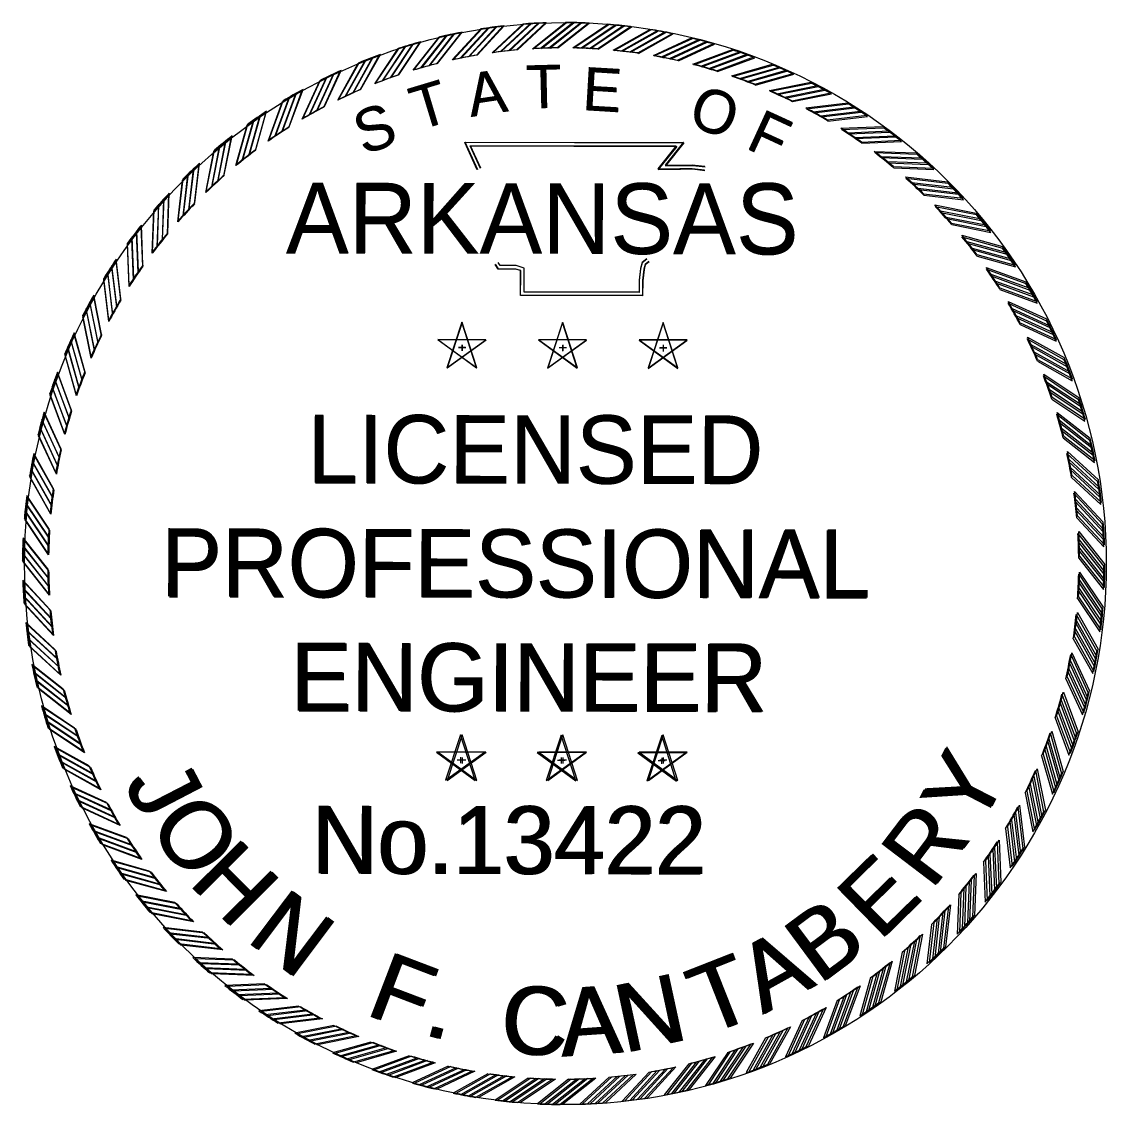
# Model space of a CAD drawing. Extents: x 0 to 19, y -0.6 to 11.5.
# Drawn here: x 17.82 to 19.023, y 7.715 to 8.916 of the extents above; entities that cross this region are included whole.
import ezdxf

# ---------------------------------------------------------------- set-up
doc = ezdxf.new("R2010")
doc.units = 0
for name, color, linetype in [('Default', 7, 'Continuous'), ('G-ANNO-STMP', 7, 'Continuous'), ('G-No Plot-Stamp-1', 7, 'Continuous')]:
    doc.layers.add(name, color=color, linetype=linetype)

# ---------------------------------------------------------------- blocks, each defined once
blk = doc.blocks.new('STAR')
at = {"layer": 'Default'}
for p, q in [((-0.0001, 0.0615), (-0.0366, -0.0504)), ((0.0362, -0.0503), (0, 0.0617)), ((0.0587, 0.0188), (-0.059, 0.0189)), ((-0.0589, 0.0188), (0.0363, -0.0505)), ((-0.0365, -0.0503), (0.0589, 0.0188)), ((-0.0085, 0), (0.009, 0)), ((0, 0.0063), (0, -0.0085))]:
    blk.add_line(p, q, dxfattribs=at)
blk = doc.blocks.new('RP')
at = {"layer": 'Default'}
for p, q in [((-0.0781, 1.2656), (0.003, 1.33)), ((-0.058, 1.2667), (0.0216, 1.3299)), ((-0.0375, 1.2674), (0.0405, 1.3294)), ((-0.0176, 1.2679), (0.059, 1.3287))]:
    blk.add_line(p, q, dxfattribs=at)
for radius, start, end in [(1.33, 87.4562, 89.8699), (1.268, 90.7933, 93.5307)]:
    blk.add_arc((0, 0), radius, start, end, dxfattribs=at)

msp = doc.modelspace()

# ---------------------------------------------------------------- linework, layer by layer
at = {"layer": 'G-ANNO-STMP'}
for points in [[(18.3256, 8.7521), (18.3116, 8.7824), (18.5542, 8.7826), (18.5339, 8.7571), (18.5504, 8.7573), (18.5641, 8.7575), (18.5779, 8.756)], [(18.3261, 8.7522), (18.3121, 8.7827), (18.5547, 8.782), (18.5344, 8.7566), (18.5509, 8.7567), (18.5646, 8.7569), (18.5784, 8.7553)], [(18.3291, 8.7537), (18.3176, 8.7786), (18.5462, 8.7787), (18.5258, 8.7532), (18.5504, 8.7535), (18.564, 8.7537), (18.5775, 8.7522)], [(18.3295, 8.7538), (18.3181, 8.7788), (18.5468, 8.7781), (18.5263, 8.7526), (18.5509, 8.7529), (18.5644, 8.753), (18.5779, 8.7515)], [(18.5135, 8.6534), (18.5084, 8.6492), (18.5066, 8.6427), (18.5052, 8.6296), (18.5052, 8.6165), (18.3775, 8.6165), (18.3775, 8.6353), (18.3775, 8.6432), (18.3687, 8.6459), (18.3509, 8.6459), (18.3487, 8.6493)], [(18.5136, 8.6529), (18.5085, 8.6488), (18.5067, 8.6423), (18.5053, 8.6292), (18.5052, 8.6161), (18.3775, 8.6165), (18.3775, 8.6353), (18.3776, 8.6432), (18.3688, 8.6459), (18.3511, 8.6459), (18.3488, 8.6494)], [(18.5159, 8.6504), (18.5118, 8.647), (18.5104, 8.642), (18.509, 8.6294), (18.509, 8.6127), (18.3736, 8.6127), (18.3736, 8.6353), (18.3736, 8.6403), (18.3681, 8.642), (18.3489, 8.642), (18.3454, 8.6472)], [(18.5161, 8.6499), (18.5119, 8.6466), (18.5105, 8.6415), (18.5091, 8.629), (18.509, 8.6122), (18.3736, 8.6127), (18.3737, 8.6353), (18.3737, 8.6403), (18.3682, 8.642), (18.349, 8.6421), (18.3456, 8.6473)]]:
    msp.add_lwpolyline(points, dxfattribs=at)
at = {"layer": 'G-No Plot-Stamp-1'}
msp.add_circle((18.4233, 8.3154), 0.6, dxfattribs=at)

# ---------------------------------------------------------------- block references
at = {"layer": 'G-ANNO-STMP'}
for name, p, xscale, yscale, rotation in [('RP', (18.4219, 8.3156), 0.45103579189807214, 0.4510357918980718, 4.500000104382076), ('RP', (18.4219, 8.3156), 0.451035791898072, 0.45103579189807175, -4.499999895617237), ('RP', (18.4209, 8.3154), 0.4510357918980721, 0.45103579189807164, -4.695800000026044), ('RP', (18.4219, 8.3156), 0.45103579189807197, 0.4510357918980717, 13.500000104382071), ('RP', (18.4209, 8.3154), 0.451035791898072, 0.45103579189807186, 13.304199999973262), ('RP', (18.4219, 8.3156), 0.45103579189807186, 0.45103579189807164, 9.000000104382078), ('RP', (18.4209, 8.3154), 0.4510357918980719, 0.4510357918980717, 8.804199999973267), ('RP', (18.4209, 8.3154), 0.451035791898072, 0.45103579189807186, 4.304199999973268), ('RP', (18.4219, 8.3156), 0.451035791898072, 0.45103579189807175, 1.0438208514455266e-07), ('RP', (18.4209, 8.3154), 0.451035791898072, 0.45103579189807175, -0.19580000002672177), ('RP', (18.4219, 8.3156), 0.4510357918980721, 0.45103579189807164, -8.999999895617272), ('RP', (18.4209, 8.3154), 0.45103579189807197, 0.45103579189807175, -9.195800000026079), ('RP', (18.4219, 8.3156), 0.4510357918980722, 0.45103579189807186, -13.499999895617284), ('RP', (18.4209, 8.3154), 0.4510357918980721, 0.4510357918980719, -13.695800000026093), ('RP', (18.4219, 8.3156), 0.45103579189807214, 0.4510357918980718, 18.000000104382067), ('RP', (18.4209, 8.3154), 0.45103579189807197, 0.4510357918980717, 17.804199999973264), ('RP', (18.4219, 8.3156), 0.45103579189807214, 0.4510357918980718, -17.99999989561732), ('RP', (18.4209, 8.3154), 0.4510357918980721, 0.4510357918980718, -18.19580000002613), ('RP', (18.4219, 8.3156), 0.45103579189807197, 0.45103579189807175, 22.500000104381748), ('RP', (18.4209, 8.3154), 0.451035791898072, 0.4510357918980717, 22.304199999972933), ('RP', (18.4219, 8.3156), 0.4510357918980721, 0.4510357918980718, -22.499999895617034), ('RP', (18.4209, 8.3154), 0.45103579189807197, 0.4510357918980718, -22.695800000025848), ('RP', (18.4219, 8.3156), 0.451035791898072, 0.45103579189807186, 27.000000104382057), ('RP', (18.4209, 8.3154), 0.45103579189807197, 0.4510357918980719, 26.804199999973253), ('RP', (18.4219, 8.3156), 0.45103579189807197, 0.4510357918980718, -26.999999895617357), ('RP', (18.4209, 8.3154), 0.45103579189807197, 0.45103579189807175, -27.19580000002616), ('RP', (18.4219, 8.3156), 0.45103579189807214, 0.45103579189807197, -31.499999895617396), ('RP', (18.4209, 8.3154), 0.4510357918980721, 0.45103579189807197, -31.695800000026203), ('RP', (18.4219, 8.3156), 0.45103579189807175, 0.45103579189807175, 31.50000010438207), ('RP', (18.4209, 8.3154), 0.4510357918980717, 0.4510357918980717, 31.30419999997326), ('RP', (18.4219, 8.3156), 0.4510357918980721, 0.451035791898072, -35.999999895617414), ('RP', (18.4209, 8.3154), 0.451035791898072, 0.45103579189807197, -36.195800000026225), ('RP', (18.4219, 8.3156), 0.4510357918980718, 0.45103579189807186, 36.00000010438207), ('RP', (18.4209, 8.3154), 0.4510357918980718, 0.45103579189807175, 35.80419999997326), ('RP', (18.4219, 8.3156), 0.4510357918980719, 0.45103579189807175, 40.50000010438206), ('RP', (18.4209, 8.3154), 0.45103579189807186, 0.45103579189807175, 40.30419999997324), ('RP', (18.4219, 8.3156), 0.45103579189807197, 0.451035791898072, -40.49999989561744), ('RP', (18.4209, 8.3154), 0.45103579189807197, 0.45103579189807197, -40.69580000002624), ('RP', (18.4209, 8.3154), 0.45103579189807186, 0.45103579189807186, 44.80419999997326), ('RP', (18.4219, 8.3156), 0.45103579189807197, 0.45103579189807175, -44.99999989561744), ('RP', (18.4209, 8.3154), 0.4510357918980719, 0.45103579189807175, -45.19580000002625), ('RP', (18.4219, 8.3156), 0.45103579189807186, 0.451035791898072, 45.00000010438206), ('RP', (18.4219, 8.3156), 0.45103579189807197, 0.451035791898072, 49.500000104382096), ('RP', (18.4209, 8.3154), 0.451035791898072, 0.451035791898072, 49.304199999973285), ('RP', (18.4219, 8.3156), 0.4510357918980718, 0.4510357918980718, -49.499999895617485), ('RP', (18.4209, 8.3154), 0.4510357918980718, 0.45103579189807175, -49.695800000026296), ('RP', (18.4219, 8.3156), 0.45103579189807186, 0.4510357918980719, 54.00000010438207), ('RP', (18.4209, 8.3154), 0.4510357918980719, 0.4510357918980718, 53.804199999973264), ('RP', (18.4219, 8.3156), 0.45103579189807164, 0.45103579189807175, -53.999999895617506), ('RP', (18.4209, 8.3154), 0.45103579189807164, 0.4510357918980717, -54.1958000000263), ('RP', (18.4209, 8.3154), 0.45103579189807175, 0.4510357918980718, 58.304199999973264), ('RP', (18.4219, 8.3156), 0.4510357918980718, 0.4510357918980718, 58.50000010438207), ('RP', (18.4219, 8.3156), 0.4510357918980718, 0.4510357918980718, -58.49999989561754), ('RP', (18.4209, 8.3154), 0.45103579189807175, 0.45103579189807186, -58.69580000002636), ('RP', (18.4219, 8.3156), 0.4510357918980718, 0.45103579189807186, -62.99999989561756), ('RP', (18.4209, 8.3154), 0.4510357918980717, 0.4510357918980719, -63.19580000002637), ('RP', (18.4209, 8.3154), 0.45103579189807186, 0.4510357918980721, 62.804199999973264), ('RP', (18.4219, 8.3156), 0.4510357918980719, 0.451035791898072, 63.00000010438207), ('STAR', (18.3085, 8.5553), 0.451035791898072, 0.45103579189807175, -0.19580000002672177), ('STAR', (18.3087, 8.5551), 0.451035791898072, 0.45103579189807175, 1.0438208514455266e-07), ('STAR', (18.4201, 8.5549), 0.451035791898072, 0.45103579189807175, -0.19580000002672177), ('STAR', (18.4203, 8.5551), 0.451035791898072, 0.45103579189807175, 1.0438208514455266e-07), ('STAR', (18.5316, 8.5545), 0.451035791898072, 0.45103579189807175, -0.19580000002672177), ('STAR', (18.5318, 8.5551), 0.451035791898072, 0.45103579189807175, 1.0438208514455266e-07), ('RP', (18.4209, 8.3154), 0.45103579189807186, 0.4510357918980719, 67.30419999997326), ('RP', (18.4219, 8.3156), 0.4510357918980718, 0.45103579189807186, 67.50000010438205), ('RP', (18.4209, 8.3154), 0.4510357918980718, 0.45103579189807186, -67.69580000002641), ('RP', (18.4219, 8.3156), 0.45103579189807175, 0.45103579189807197, -67.49999989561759), ('RP', (18.4209, 8.3154), 0.4510357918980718, 0.4510357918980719, -72.19580000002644), ('RP', (18.4219, 8.3156), 0.4510357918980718, 0.45103579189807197, -71.99999989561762), ('RP', (18.4209, 8.3154), 0.45103579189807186, 0.451035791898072, 71.80419999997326), ('RP', (18.4219, 8.3156), 0.4510357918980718, 0.45103579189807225, 72.00000010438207), ('RP', (18.4209, 8.3154), 0.4510357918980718, 0.4510357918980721, 76.30419999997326), ('RP', (18.4209, 8.3154), 0.4510357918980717, 0.4510357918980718, -76.69580000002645), ('RP', (18.4219, 8.3156), 0.4510357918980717, 0.4510357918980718, -76.49999989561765), ('RP', (18.4219, 8.3156), 0.4510357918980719, 0.451035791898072, 76.50000010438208), ('RP', (18.4209, 8.3154), 0.4510357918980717, 0.45103579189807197, 80.80419999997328), ('RP', (18.4219, 8.3156), 0.4510357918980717, 0.451035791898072, 81.0000001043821), ('RP', (18.4209, 8.3154), 0.4510357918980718, 0.45103579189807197, -81.19580000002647), ('RP', (18.4219, 8.3156), 0.45103579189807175, 0.45103579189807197, -80.99999989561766), ('RP', (18.4209, 8.3154), 0.4510357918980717, 0.4510357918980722, 85.30419999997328), ('RP', (18.4219, 8.3156), 0.4510357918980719, 0.4510357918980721, 85.5000001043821), ('RP', (18.4209, 8.3154), 0.4510357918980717, 0.4510357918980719, -85.69580000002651), ('RP', (18.4219, 8.3156), 0.45103579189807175, 0.4510357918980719, -85.49999989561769), ('RP', (18.4219, 8.3156), 0.4510357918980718, 0.45103579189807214, -89.99999989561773), ('RP', (18.4209, 8.3154), 0.45103579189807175, 0.451035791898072, 89.80419999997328), ('RP', (18.4219, 8.3156), 0.45103579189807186, 0.45103579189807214, 90.0000001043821), ('RP', (18.4209, 8.3154), 0.45103579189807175, 0.451035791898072, -90.19580000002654), ('RP', (18.4209, 8.3154), 0.45103579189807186, 0.451035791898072, -94.69580000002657), ('RP', (18.4219, 8.3156), 0.45103579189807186, 0.451035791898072, -94.49999989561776), ('RP', (18.4209, 8.3154), 0.45103579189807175, 0.4510357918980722, 94.30419999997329), ('RP', (18.4219, 8.3156), 0.45103579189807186, 0.4510357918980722, 94.5000001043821), ('RP', (18.4209, 8.3154), 0.4510357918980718, 0.45103579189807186, 98.8041999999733), ('RP', (18.4209, 8.3154), 0.45103579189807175, 0.45103579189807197, -99.19580000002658), ('RP', (18.4219, 8.3156), 0.4510357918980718, 0.4510357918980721, -98.99999989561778), ('RP', (18.4219, 8.3156), 0.45103579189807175, 0.4510357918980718, 99.0000001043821), ('RP', (18.4209, 8.3154), 0.4510357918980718, 0.4510357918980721, 103.30419999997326), ('RP', (18.4219, 8.3156), 0.45103579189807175, 0.451035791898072, 103.50000010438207), ('RP', (18.4209, 8.3154), 0.4510357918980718, 0.4510357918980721, -103.69580000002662), ('RP', (18.4219, 8.3156), 0.45103579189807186, 0.45103579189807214, -103.49999989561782), ('RP', (18.4209, 8.3154), 0.45103579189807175, 0.45103579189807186, -108.19580000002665), ('RP', (18.4219, 8.3156), 0.4510357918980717, 0.451035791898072, -107.99999989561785), ('RP', (18.4209, 8.3154), 0.45103579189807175, 0.4510357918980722, 107.80419999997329), ('RP', (18.4219, 8.3156), 0.45103579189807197, 0.45103579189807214, 108.0000001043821), ('RP', (18.4209, 8.3154), 0.45103579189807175, 0.45103579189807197, 112.30419999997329), ('RP', (18.4219, 8.3156), 0.4510357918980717, 0.45103579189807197, 112.5000001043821), ('STAR', (18.3069, 8.0978), 0.451035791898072, 0.45103579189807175, -0.19580000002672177), ('STAR', (18.3087, 8.0976), 0.451035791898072, 0.45103579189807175, 1.0438208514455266e-07), ('STAR', (18.4185, 8.0974), 0.451035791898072, 0.45103579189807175, -0.19580000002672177), ('STAR', (18.4203, 8.0976), 0.451035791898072, 0.45103579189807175, 1.0438208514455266e-07), ('STAR', (18.5301, 8.097), 0.451035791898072, 0.45103579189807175, -0.19580000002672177), ('STAR', (18.5318, 8.0976), 0.451035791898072, 0.45103579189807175, 1.0438208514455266e-07), ('RP', (18.4209, 8.3154), 0.4510357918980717, 0.4510357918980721, -112.69580000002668), ('RP', (18.4219, 8.3156), 0.45103579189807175, 0.4510357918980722, -112.49999989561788), ('RP', (18.4209, 8.3154), 0.4510357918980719, 0.4510357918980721, -117.19580000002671), ('RP', (18.4219, 8.3156), 0.451035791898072, 0.4510357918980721, -116.9999998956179), ('RP', (18.4209, 8.3154), 0.4510357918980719, 0.45103579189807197, 116.80419999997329), ('RP', (18.4219, 8.3156), 0.4510357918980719, 0.45103579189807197, 117.0000001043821), ('RP', (18.4209, 8.3154), 0.45103579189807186, 0.45103579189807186, 121.30419999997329), ('RP', (18.4219, 8.3156), 0.45103579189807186, 0.45103579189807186, 121.5000001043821), ('RP', (18.4209, 8.3154), 0.4510357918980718, 0.4510357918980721, -121.69580000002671), ('RP', (18.4219, 8.3156), 0.4510357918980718, 0.4510357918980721, -121.4999998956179), ('RP', (18.4209, 8.3154), 0.45103579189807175, 0.45103579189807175, 125.80419999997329), ('RP', (18.4219, 8.3156), 0.4510357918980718, 0.4510357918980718, 126.00000010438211), ('RP', (18.4209, 8.3154), 0.4510357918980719, 0.45103579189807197, -126.19580000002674), ('RP', (18.4219, 8.3156), 0.45103579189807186, 0.45103579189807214, -125.99999989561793), ('RP', (18.4209, 8.3154), 0.4510357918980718, 0.4510357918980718, 130.3041999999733), ('RP', (18.4209, 8.3154), 0.45103579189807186, 0.45103579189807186, -130.6958000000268), ('RP', (18.4219, 8.3156), 0.45103579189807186, 0.4510357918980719, -130.49999989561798), ('RP', (18.4219, 8.3156), 0.4510357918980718, 0.45103579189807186, 130.50000010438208), ('RP', (18.4209, 8.3154), 0.45103579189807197, 0.45103579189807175, 134.80419999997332), ('RP', (18.4219, 8.3156), 0.45103579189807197, 0.4510357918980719, 135.00000010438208), ('RP', (18.4209, 8.3154), 0.45103579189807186, 0.45103579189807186, -135.19580000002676), ('RP', (18.4219, 8.3156), 0.45103579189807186, 0.451035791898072, -134.99999989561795), ('RP', (18.4209, 8.3154), 0.45103579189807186, 0.45103579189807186, 139.30419999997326), ('RP', (18.4219, 8.3156), 0.4510357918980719, 0.45103579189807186, 139.50000010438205), ('RP', (18.4209, 8.3154), 0.4510357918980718, 0.45103579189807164, -139.69580000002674), ('RP', (18.4219, 8.3156), 0.4510357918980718, 0.45103579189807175, -139.49999989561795), ('RP', (18.4209, 8.3154), 0.451035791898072, 0.45103579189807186, 143.8041999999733), ('RP', (18.4219, 8.3156), 0.4510357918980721, 0.4510357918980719, 144.00000010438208), ('RP', (18.4209, 8.3154), 0.4510357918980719, 0.4510357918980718, -144.19580000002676), ('RP', (18.4219, 8.3156), 0.45103579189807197, 0.45103579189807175, -143.99999989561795), ('RP', (18.4209, 8.3154), 0.45103579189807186, 0.45103579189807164, -148.69580000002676), ('RP', (18.4219, 8.3156), 0.45103579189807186, 0.45103579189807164, -148.49999989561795), ('RP', (18.4209, 8.3154), 0.4510357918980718, 0.45103579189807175, 148.3041999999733), ('RP', (18.4219, 8.3156), 0.4510357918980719, 0.4510357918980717, 148.50000010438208), ('RP', (18.4209, 8.3154), 0.45103579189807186, 0.45103579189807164, -153.1958000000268), ('RP', (18.4219, 8.3156), 0.4510357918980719, 0.4510357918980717, -152.99999989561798), ('RP', (18.4209, 8.3154), 0.4510357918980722, 0.4510357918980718, 152.8041999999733), ('RP', (18.4219, 8.3156), 0.4510357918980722, 0.45103579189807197, 153.00000010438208), ('RP', (18.4209, 8.3154), 0.45103579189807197, 0.4510357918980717, 157.3041999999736), ('RP', (18.4219, 8.3156), 0.4510357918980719, 0.4510357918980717, 157.50000010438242), ('RP', (18.4209, 8.3154), 0.451035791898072, 0.4510357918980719, -157.6958000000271), ('RP', (18.4219, 8.3156), 0.45103579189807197, 0.45103579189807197, -157.4999998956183), ('RP', (18.4209, 8.3154), 0.4510357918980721, 0.4510357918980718, 161.8041999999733), ('RP', (18.4219, 8.3156), 0.4510357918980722, 0.4510357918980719, 162.00000010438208), ('RP', (18.4209, 8.3154), 0.45103579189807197, 0.4510357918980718, -162.19580000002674), ('RP', (18.4219, 8.3156), 0.45103579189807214, 0.45103579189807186, -161.99999989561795), ('RP', (18.4209, 8.3154), 0.4510357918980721, 0.4510357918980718, 166.3041999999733), ('RP', (18.4219, 8.3156), 0.4510357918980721, 0.4510357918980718, 166.50000010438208), ('RP', (18.4209, 8.3154), 0.451035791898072, 0.45103579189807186, -166.69580000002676), ('RP', (18.4219, 8.3156), 0.45103579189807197, 0.4510357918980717, -166.49999989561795), ('RP', (18.4209, 8.3154), 0.45103579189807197, 0.4510357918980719, 170.8041999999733), ('RP', (18.4219, 8.3156), 0.45103579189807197, 0.4510357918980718, 171.00000010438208), ('RP', (18.4209, 8.3154), 0.451035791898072, 0.45103579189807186, 175.3041999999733), ('RP', (18.4219, 8.3156), 0.4510357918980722, 0.4510357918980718, 175.50000010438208), ('RP', (18.4209, 8.3154), 0.45103579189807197, 0.4510357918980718, -175.69580000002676), ('RP', (18.4219, 8.3156), 0.45103579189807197, 0.45103579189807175, -175.49999989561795), ('RP', (18.4209, 8.3154), 0.4510357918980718, 0.4510357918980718, -171.19580000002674), ('RP', (18.4219, 8.3156), 0.45103579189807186, 0.45103579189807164, -170.99999989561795), ('RP', (18.4209, 8.3154), 0.451035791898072, 0.45103579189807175, 179.8041999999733), ('RP', (18.4219, 8.3156), 0.45103579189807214, 0.45103579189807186, -179.99999989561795)]:
    msp.add_blockref(name, p, dxfattribs=dict(at, xscale=xscale, yscale=yscale, rotation=rotation))

# ---------------------------------------------------------------- texts
for s, height, rotation, p in [('T', 0.0479, 1.4789, (18.38, 8.82)), ('T', 0.0479, 1.2831, (18.3807, 8.82)), ('A', 0.0479, 8.6788, (18.3182, 8.8105)), ('A', 0.0479, 8.483, (18.3189, 8.8107)), ('E', 0.0479, 356.672, (18.4412, 8.8185)), ('E', 0.0479, 356.4762, (18.4419, 8.8183)), ('T', 0.0479, 16.9015, (18.2601, 8.7953)), ('T', 0.0479, 16.7057, (18.2607, 8.7957)), ('O', 0.0479, 341.2218, (18.5574, 8.8021)), ('O', 0.0479, 341.026, (18.5581, 8.8015)), ('S', 0.0479, 19.7726, (18.1992, 8.768)), ('S', 0.0479, 19.5768, (18.1998, 8.7686)), ('F', 0.0479, 335.3628, (18.6219, 8.7769)), ('F', 0.0479, 335.167, (18.6225, 8.7761)), ('ARKANSAS', 0.0781, 0, (18.1132, 8.6591)), ('ARKANSAS', 0.0781, 359.8042, (18.1134, 8.66)), ('LICENSED', 0.07561, 359.8042, (18.1368, 8.405)), ('LICENSED', 0.07561, 0, (18.1375, 8.4042)), ('PROFESSIONAL', 0.075612, 359.8042, (17.9743, 8.2791)), ('PROFESSIONAL', 0.075612, 0, (17.9755, 8.2777)), ('ENGINEER', 0.07561, 359.8042, (18.1179, 8.1522)), ('ENGINEER', 0.07561, 0, (18.1195, 8.1513)), ('Y', 0.0756, 62.5392, (18.8819, 8.0186)), ('Y', 0.0756, 62.735, (18.8839, 8.0204)), ('J', 0.0756, 297.2813, (17.9322, 8.0724)), ('J', 0.0756, 297.4771, (17.934, 8.0709)), ('O', 0.0756, 304.1899, (17.959, 8.026)), ('O', 0.0756, 304.3857, (17.961, 8.0246)), ('No.13422', 0.07531, 359.8042, (18.1412, 7.9718)), ('No.13422', 0.07531, 0, (18.1434, 7.9711)), ('R', 0.0756, 52.7437, (18.8291, 7.9521)), ('R', 0.0756, 52.9395, (18.8313, 7.9536)), ('H', 0.0756, 314.7447, (18.0036, 7.9609)), ('H', 0.0756, 314.9405, (18.0058, 7.9596)), ('E', 0.0756, 44.306, (18.7715, 7.8958)), ('E', 0.0756, 44.5018, (18.7739, 7.8971)), ('N', 0.0756, 322.9417, (18.0674, 7.8976)), ('N', 0.0756, 323.1375, (18.0698, 7.8966)), ('B', 0.0756, 36.505, (18.7047, 7.8477)), ('B', 0.0756, 36.7008, (18.7074, 7.8488)), ('A', 0.0756, 28.8562, (18.6419, 7.8147)), ('A', 0.0756, 29.052, (18.6447, 7.8156)), ('F', 0.0756, 339.0288, (18.1994, 7.8157)), ('F', 0.0756, 339.2246, (18.2021, 7.8152)), ('T', 0.0756, 21.4329, (18.5791, 7.791)), ('T', 0.0756, 21.6287, (18.5819, 7.7917)), ('N', 0.0756, 12.0703, (18.4879, 7.7722)), ('N', 0.0756, 12.2661, (18.4907, 7.7726)), ('C', 0.0756, 356.1028, (18.3494, 7.7733)), ('C', 0.0756, 356.2986, (18.3523, 7.7732)), ('A', 0.0756, 3.9092, (18.4187, 7.7683)), ('A', 0.0756, 4.105, (18.4216, 7.7685)), ('.', 0.0756, 344.7037, (18.2639, 7.7934)), ('.', 0.0756, 344.8995, (18.2667, 7.793))]:
    msp.add_text(s, height=height, rotation=rotation, dxfattribs=at).set_placement(p)

doc.saveas('drawing.dxf')
